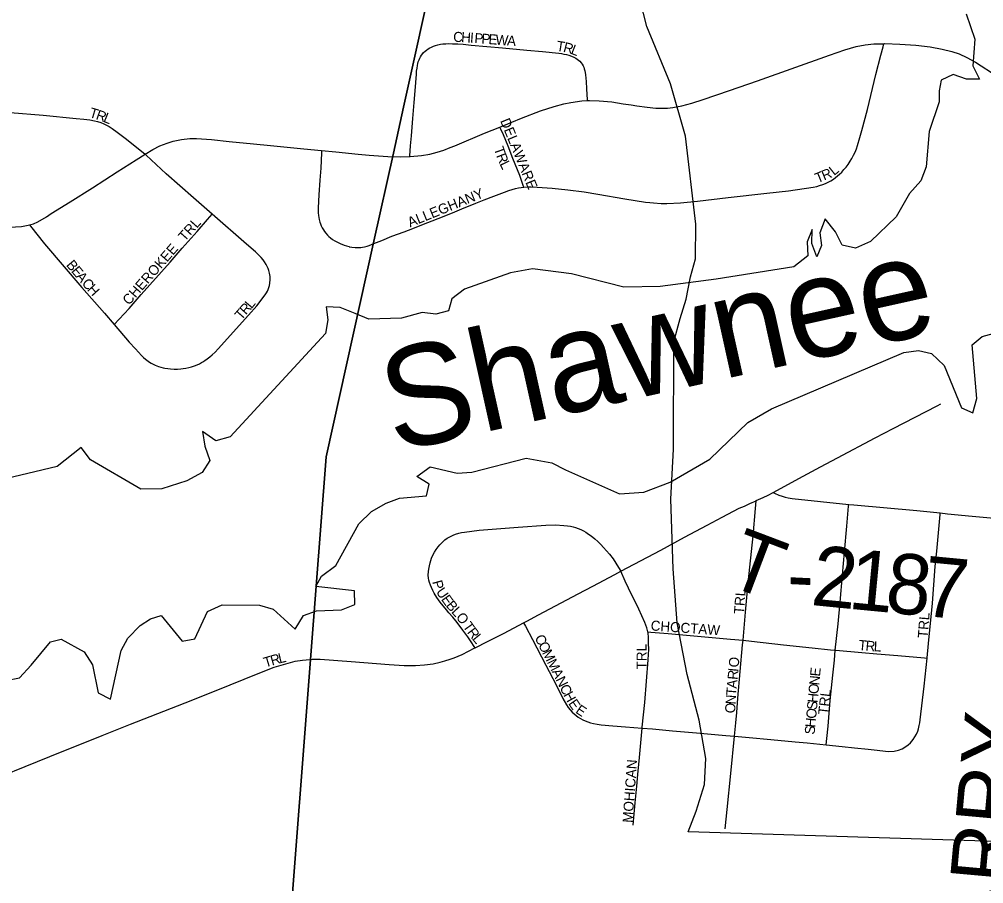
# Model space of a CAD drawing. Extents: x -5.4 to 49.9, y 13.2 to 48.4.
# Drawn here: x 27.015 to 27.924, y 42.711 to 43.526 of the extents above; entities that cross this region are included whole.
import ezdxf

# ---------------------------------------------------------------- set-up
doc = ezdxf.new("R2010")
doc.units = 0
for name, color, linetype in [('GM_X_Corporation', 7, 'Continuous'), ('GM_X_County_Road_Text', 7, 'Continuous'), ('GM_X_Major_Lake', 7, 'Continuous'), ('GM_X_Major_Lake_Text', 7, 'Continuous'), ('GM_X_Township', 7, 'Continuous'), ('GM_X_Township_Road', 7, 'Continuous'), ('GM_X_Township_Road_Text', 7, 'Continuous'), ('GM_X_Township_Subdivision', 7, 'Continuous'), ('GM_X_Township_Subdivision_Text', 7, 'Continuous')]:
    doc.layers.add(name, color=color, linetype=linetype)

msp = doc.modelspace()

# ---------------------------------------------------------------- linework, layer by layer
at = {"layer": 'GM_X_Corporation'}
msp.add_lwpolyline([(28.56624, 42.73136), (27.6459, 42.76038), (27.65346, 42.77968), (27.66125, 42.80482), (27.66239, 42.8295), (27.65632, 42.86559), (27.64493, 42.90851), (27.63544, 42.95751), (27.63165, 43.0084), (27.62938, 43.07411), (27.63204, 43.1212), (27.63225, 43.22236), (27.63841, 43.24417), (27.64404, 43.26266), (27.64805, 43.28356), (27.65287, 43.30045), (27.65294, 43.33325), (27.64345, 43.4163), (27.62902, 43.46569), (27.607, 43.51963), (27.59725, 43.55802)], dxfattribs=at)
at = {"layer": 'GM_X_Major_Lake'}
for points in [[(27.90786, 43.5315), (27.91605, 43.50779), (27.91435, 43.4824), (27.92052, 43.47012), (27.90838, 43.47001), (27.89559, 43.47447), (27.88448, 43.46902), (27.88236, 43.45882), (27.88251, 43.44857), (27.87317, 43.4207), (27.87015, 43.38737), (27.86531, 43.37419), (27.85442, 43.36229), (27.8418, 43.34018), (27.81778, 43.3168), (27.80361, 43.31066), (27.79116, 43.31359), (27.78461, 43.32588), (27.77503, 43.33823), (27.76981, 43.32506), (27.77144, 43.31326), (27.76703, 43.30236), (27.76238, 43.31498), (27.76268, 43.32826), (27.75787, 43.3166), (27.75871, 43.3033), (27.74559, 43.29296), (27.67216, 43.2813), (27.61932, 43.27449), (27.58518, 43.27372), (27.5358, 43.28657), (27.49913, 43.29117), (27.4782, 43.28745), (27.43502, 43.27208), (27.42306, 43.26286), (27.41978, 43.25155), (27.40795, 43.24839), (27.39509, 43.24982), (27.37564, 43.24455), (27.34492, 43.24371), (27.33176, 43.24893), (27.31786, 43.25455), (27.30461, 43.25522), (27.30623, 43.24304), (27.30405, 43.23019), (27.21392, 43.13275), (27.20057, 43.12887), (27.18788, 43.13787), (27.19022, 43.12378), (27.19485, 43.1104), (27.18778, 43.09917), (27.17319, 43.09114), (27.14952, 43.08369), (27.1298, 43.08337), (27.08227, 43.11098), (27.07343, 43.12255), (27.05104, 43.10483), (26.9954, 43.09164)], [(27.00256, 42.90289), (27.01552, 42.90564), (27.0264, 42.91754), (27.04471, 42.93953), (27.05461, 42.94197), (27.07634, 42.9301), (27.08441, 42.91778), (27.08951, 42.89149), (27.10112, 42.88554), (27.11124, 42.93123), (27.11757, 42.94286), (27.12921, 42.95475), (27.13882, 42.96098), (27.14913, 42.96417), (27.16869, 42.94022), (27.18086, 42.94223), (27.19281, 42.96815), (27.2066, 42.9743), (27.24185, 42.9739), (27.25465, 42.9702), (27.27547, 42.95153), (27.28334, 42.96426), (27.29556, 42.96855), (27.31909, 42.96955), (27.33171, 42.97458), (27.33124, 42.98749), (27.29494, 42.99171), (27.30009, 43.00146), (27.31358, 43.01141), (27.33531, 43.05077), (27.34731, 43.06227), (27.36114, 43.07032), (27.37376, 43.07497), (27.3992, 43.07707), (27.40172, 43.08802), (27.39013, 43.09548), (27.40246, 43.10432), (27.42811, 43.09844), (27.44178, 43.09928), (27.49325, 43.11257), (27.51742, 43.10825), (27.53016, 43.10151), (27.58122, 43.07914), (27.604, 43.08054), (27.62885, 43.08986), (27.66611, 43.11181), (27.70214, 43.14631), (27.72441, 43.1591), (27.84918, 43.21214), (27.86287, 43.21412), (27.87532, 43.21119), (27.8872, 43.19992), (27.90337, 43.1601), (27.91426, 43.15531), (27.91797, 43.16889), (27.91341, 43.21946), (27.92306, 43.22721), (27.95625, 43.23635)]]:
    msp.add_lwpolyline(points, dxfattribs=at)
at = {"layer": 'GM_X_Township'}
for points in [[(27.24718, 42.36774), (27.29015, 42.92693), (27.30451, 43.11387), (27.34959, 43.3173), (27.36795, 43.40015), (27.3776, 43.4437), (27.55837, 44.25954)], [(27.55837, 44.25954), (27.3776, 43.4437), (27.36795, 43.40015), (27.34959, 43.3173), (27.30451, 43.11387), (27.29015, 42.92693), (27.24718, 42.36774)]]:
    msp.add_lwpolyline(points, dxfattribs=at)
at = {"layer": 'GM_X_Township_Road'}
for points in [[(27.55082, 43.44977), (27.55286, 43.4499), (27.56203, 43.44954), (27.57372, 43.44848), (27.58467, 43.44686), (27.59194, 43.44567), (27.59742, 43.44484), (27.60723, 43.44341), (27.61528, 43.4427), (27.62217, 43.44258), (27.62648, 43.44275), (27.63144, 43.44325), (27.63976, 43.44478), (27.6494, 43.44726), (27.66004, 43.45071), (27.68472, 43.45924), (27.71111, 43.46841), (27.77896, 43.49268), (27.79366, 43.49761), (27.80436, 43.50063), (27.81281, 43.50231), (27.82076, 43.50318), (27.83034, 43.50342)], [(27.83034, 43.50342), (27.83124, 43.50345), (27.84549, 43.50311), (27.86032, 43.50207), (27.87383, 43.50041), (27.8854, 43.49834), (27.89437, 43.4961), (27.90133, 43.49371), (27.9086, 43.49041), (27.91666, 43.48587), (27.93699, 43.47281)], [(27.46826, 43.42481), (27.47969, 43.42951), (27.48885, 43.43316), (27.50665, 43.44001), (27.51955, 43.44429), (27.52849, 43.44659), (27.53514, 43.44793), (27.54553, 43.44941), (27.55082, 43.44977)], [(27.38333, 43.39701), (27.38376, 43.39702), (27.39435, 43.39801), (27.40237, 43.39934), (27.40907, 43.401), (27.4156, 43.40316), (27.42137, 43.40543), (27.42598, 43.40725), (27.45396, 43.41893), (27.46826, 43.42481)], [(27.13392, 43.39922), (27.14111, 43.40367), (27.14771, 43.40697), (27.15454, 43.40974), (27.16036, 43.41155), (27.16817, 43.41307), (27.17611, 43.41398), (27.1822, 43.41412), (27.19635, 43.41297), (27.21302, 43.4113), (27.23592, 43.40911), (27.25195, 43.4075), (27.28341, 43.40438), (27.30017, 43.40268)], [(27.02492, 43.33258), (27.02854, 43.33368), (27.0326, 43.33546), (27.04079, 43.3401), (27.04544, 43.34322), (27.06314, 43.35436), (27.08425, 43.36764), (27.10757, 43.3825), (27.12534, 43.39391), (27.13392, 43.39922)], [(27.30017, 43.40268), (27.31366, 43.40131), (27.33476, 43.39929)], [(27.33476, 43.39929), (27.34519, 43.3983), (27.36256, 43.39702), (27.37441, 43.39673), (27.38333, 43.39701)], [(26.99436, 43.32999), (27.0118, 43.33078), (27.01744, 43.33118), (27.02367, 43.33221), (27.02492, 43.33258)], [(27.72606, 43.08009), (27.72737, 43.07951), (27.73143, 43.07773), (27.7343, 43.07664), (27.73727, 43.07584), (27.74014, 43.07525), (27.74397, 43.07468), (27.79724, 43.069)], [(27.79724, 43.069), (27.80209, 43.06849), (27.86153, 43.06314), (27.88335, 43.06095)], [(27.88335, 43.06095), (27.89044, 43.06024), (27.91351, 43.05792), (27.96863, 43.05303), (27.98907, 43.05107), (28.00831, 43.0493), (28.01008, 43.04914)]]:
    msp.add_lwpolyline(points, dxfattribs=at)
at = {"layer": 'GM_X_Township_Subdivision'}
for points in [[(27.38333, 43.39701), (27.38339, 43.39774), (27.38415, 43.40712), (27.38491, 43.41662), (27.38623, 43.43299), (27.38749, 43.448), (27.38836, 43.45898), (27.38956, 43.47453), (27.38981, 43.47754), (27.3902, 43.48018), (27.39067, 43.48294), (27.39103, 43.48467), (27.39141, 43.48627), (27.39212, 43.48814), (27.39289, 43.48974), (27.39356, 43.49098), (27.39456, 43.49263), (27.39557, 43.4941), (27.39642, 43.49513), (27.39774, 43.49631), (27.39912, 43.49744), (27.40066, 43.49856), (27.40223, 43.49951), (27.40374, 43.50027), (27.4056, 43.50105), (27.40753, 43.50174), (27.40975, 43.50232), (27.41228, 43.5029), (27.41465, 43.50316), (27.41729, 43.50335), (27.42022, 43.50347), (27.42371, 43.50338), (27.42878, 43.50316), (27.43359, 43.50284), (27.44124, 43.50213), (27.47088, 43.49941), (27.49372, 43.49742), (27.50853, 43.4961), (27.52393, 43.49442), (27.52639, 43.49404), (27.52848, 43.49365), (27.53126, 43.49308), (27.53343, 43.49257), (27.53587, 43.4918), (27.53799, 43.49083), (27.53985, 43.48987), (27.54126, 43.48891), (27.54254, 43.48788), (27.54362, 43.48686), (27.54498, 43.48544), (27.54597, 43.48402), (27.54678, 43.48255), (27.54733, 43.48129), (27.54776, 43.47979), (27.54833, 43.47775), (27.5489, 43.47434), (27.54933, 43.47061), (27.54957, 43.46796), (27.5501, 43.46058), (27.55076, 43.45064), (27.55082, 43.44977)], [(27.49086, 43.36817), (27.49401, 43.3684), (27.49775, 43.36842), (27.50335, 43.36816), (27.50834, 43.36786), (27.51305, 43.3675), (27.51763, 43.36715), (27.53236, 43.36563), (27.54776, 43.3638), (27.5606, 43.36163), (27.58614, 43.357), (27.60571, 43.35402), (27.60965, 43.35352), (27.61327, 43.35326), (27.62042, 43.35287), (27.6256, 43.35283), (27.63856, 43.35344), (27.65461, 43.355), (27.68361, 43.35838), (27.72002, 43.36247), (27.74041, 43.36482), (27.76369, 43.36824), (27.76699, 43.3689), (27.76964, 43.36965), (27.77266, 43.37062), (27.77539, 43.37167), (27.78028, 43.37411), (27.78293, 43.3758), (27.7848, 43.37715), (27.78853, 43.38026), (27.79066, 43.38238), (27.79273, 43.38464), (27.79469, 43.38698), (27.79651, 43.38942), (27.79863, 43.39257), (27.80009, 43.39512), (27.80176, 43.39816), (27.80316, 43.40101), (27.80447, 43.40441), (27.80551, 43.40728), (27.80768, 43.41485), (27.80957, 43.42159), (27.81474, 43.44132), (27.82288, 43.47451), (27.82755, 43.49262), (27.82954, 43.50034), (27.83034, 43.50342)], [(26.98934, 43.44019), (27.00649, 43.43859), (27.03764, 43.43588), (27.06877, 43.43298), (27.07594, 43.43232), (27.08162, 43.43152), (27.08606, 43.43062), (27.08894, 43.42996), (27.09214, 43.42897), (27.09502, 43.42774), (27.09749, 43.42651), (27.10003, 43.42519), (27.10283, 43.42346), (27.10764, 43.41985), (27.1164, 43.41327), (27.13392, 43.39922)], [(27.49086, 43.36817), (27.49063, 43.36883), (27.48895, 43.37361), (27.487, 43.37902), (27.4806, 43.39531), (27.47602, 43.40685), (27.47178, 43.41754), (27.46887, 43.42356), (27.46826, 43.42481)], [(27.19709, 43.34282), (27.17941, 43.3582), (27.15356, 43.38058), (27.13481, 43.39839), (27.13392, 43.39922)], [(27.30017, 43.40268), (27.30008, 43.40063), (27.29949, 43.38618), (27.29862, 43.37485), (27.29757, 43.36092), (27.29725, 43.35483), (27.29692, 43.34835), (27.29698, 43.34588), (27.2971, 43.34379), (27.29726, 43.3414), (27.29759, 43.33943), (27.29789, 43.33776), (27.29858, 43.33507), (27.29909, 43.33358), (27.29977, 43.33178), (27.3008, 43.32973), (27.30191, 43.32792), (27.30299, 43.3262), (27.30421, 43.32463), (27.30567, 43.32299), (27.30712, 43.32159), (27.30865, 43.32024), (27.31062, 43.31887), (27.31282, 43.31761), (27.31532, 43.31636), (27.31773, 43.31516), (27.32168, 43.31355), (27.32377, 43.31271), (27.32608, 43.31206)], [(27.32608, 43.31206), (27.32626, 43.31202), (27.32867, 43.31156), (27.33183, 43.31123), (27.33356, 43.31111), (27.3359, 43.31123), (27.3373, 43.31131), (27.33881, 43.31152), (27.34079, 43.31193), (27.34321, 43.31263), (27.34507, 43.31325), (27.34938, 43.31497), (27.35689, 43.31797), (27.36658, 43.32185), (27.378, 43.32613), (27.38627, 43.32927), (27.39476, 43.33248), (27.41025, 43.33865), (27.42359, 43.34408), (27.43249, 43.34781), (27.44555, 43.35308), (27.45353, 43.35613), (27.46261, 43.35961), (27.4726, 43.36351), (27.47676, 43.36497), (27.47981, 43.36596), (27.4832, 43.36688), (27.48587, 43.36752), (27.48834, 43.36791), (27.49086, 43.36817)], [(27.10474, 43.23854), (27.11894, 43.22185), (27.1247, 43.21569), (27.13043, 43.20941), (27.13248, 43.20738), (27.13413, 43.20592), (27.13548, 43.20488), (27.13668, 43.20398), (27.13789, 43.20317), (27.13943, 43.20218), (27.14149, 43.20111), (27.14349, 43.20019), (27.14646, 43.19905), (27.14876, 43.19835), (27.15098, 43.19781), (27.15258, 43.19753), (27.15528, 43.19715), (27.15793, 43.19687), (27.16138, 43.19664), (27.16433, 43.19663), (27.16749, 43.19676), (27.16985, 43.19704), (27.17235, 43.1974), (27.17506, 43.19798), (27.17772, 43.19872), (27.18032, 43.19963), (27.18283, 43.20061), (27.18509, 43.20164), (27.18701, 43.20268), (27.18834, 43.20341), (27.19027, 43.20472), (27.19236, 43.20615), (27.195, 43.20826), (27.19709, 43.2101), (27.19976, 43.21265), (27.2028, 43.21564), (27.23142, 43.24752), (27.23918, 43.25633), (27.24717, 43.26653), (27.24832, 43.26843), (27.24924, 43.27017), (27.24989, 43.27171), (27.25049, 43.27353), (27.25104, 43.27534), (27.25136, 43.27764), (27.2517, 43.28109), (27.25161, 43.28397), (27.25104, 43.28709), (27.25049, 43.28951), (27.24989, 43.29136), (27.24888, 43.2934), (27.24799, 43.29523), (27.24649, 43.29761), (27.24504, 43.29966), (27.24313, 43.30191), (27.23793, 43.30715), (27.22959, 43.31453), (27.19709, 43.34282)], [(27.10474, 43.23854), (27.10954, 43.24374), (27.1188, 43.25377), (27.13026, 43.26685), (27.15737, 43.29754), (27.16891, 43.31054), (27.18294, 43.32626), (27.1926, 43.33756), (27.19709, 43.34282)], [(27.02492, 43.33258), (27.02589, 43.33135), (27.0391, 43.31459), (27.07429, 43.2736), (27.0956, 43.24929), (27.10474, 43.23854)], [(27.72606, 43.08009), (27.75416, 43.09569), (27.77059, 43.10447), (27.7865, 43.11287), (27.82217, 43.13174), (27.83923, 43.14067), (27.88065, 43.16203), (27.88396, 43.1637)], [(27.70985, 43.0725), (27.71, 43.07257), (27.71641, 43.0754), (27.72109, 43.07767), (27.72606, 43.08009)], [(27.58247, 43.00602), (27.61997, 43.02589), (27.64233, 43.03804), (27.66362, 43.0496), (27.67796, 43.05705), (27.694, 43.06533), (27.69878, 43.06751), (27.70384, 43.06998), (27.70985, 43.0725)], [(27.69754, 42.94092), (27.69984, 42.96743), (27.70236, 42.99492), (27.70701, 43.03932), (27.70924, 43.06531), (27.70985, 43.0725)], [(27.78452, 42.93154), (27.7872, 42.95647), (27.78908, 42.97682), (27.79147, 43.00257), (27.79326, 43.02409), (27.79542, 43.04854), (27.79709, 43.06741), (27.79724, 43.069)], [(27.87112, 42.92412), (27.87115, 42.92442), (27.87242, 42.93778), (27.87604, 42.97581), (27.87869, 43.01062), (27.8801, 43.0249), (27.88327, 43.05941), (27.88335, 43.06095)], [(27.44487, 42.93386), (27.44409, 42.93508), (27.44124, 42.93948), (27.43798, 42.94421), (27.43349, 42.95049), (27.42984, 42.95527), (27.42673, 42.95913), (27.4239, 42.96264), (27.4203, 42.96683), (27.41795, 42.96959), (27.41215, 42.9768), (27.40892, 42.98129), (27.40634, 42.9854), (27.40504, 42.98783), (27.40374, 42.99052), (27.40283, 42.9928), (27.40202, 42.99541), (27.40145, 42.99754), (27.40109, 42.99955), (27.4008, 43.00218), (27.40096, 43.00561), (27.40131, 43.00789), (27.40186, 43.01115), (27.40251, 43.01393), (27.40316, 43.01621), (27.40398, 43.01841), (27.40512, 43.02102), (27.40675, 43.02412), (27.40838, 43.0264), (27.4102, 43.02896), (27.41173, 43.03097), (27.4138, 43.03309), (27.41645, 43.03548), (27.41874, 43.03708), (27.42054, 43.0381), (27.42224, 43.03896), (27.42431, 43.03999), (27.42648, 43.04092), (27.42948, 43.04179), (27.43219, 43.04246), (27.43483, 43.04298), (27.44895, 43.04473), (27.48548, 43.0476), (27.5115, 43.04944), (27.52075, 43.04964), (27.52873, 43.04921), (27.53199, 43.04891), (27.53501, 43.04842), (27.53754, 43.04785), (27.5395, 43.04727), (27.54203, 43.04638), (27.54462, 43.0453), (27.547, 43.0441), (27.54947, 43.04275), (27.55197, 43.04108), (27.55447, 43.03932), (27.55784, 43.03644), (27.56054, 43.03414), (27.56339, 43.03137), (27.56616, 43.02849), (27.57152, 43.02207), (27.57505, 43.0176), (27.57763, 43.01376), (27.58023, 43.0096), (27.58247, 43.00602)], [(27.49073, 42.95744), (27.49377, 42.95905), (27.5047, 42.96494), (27.54201, 42.98468), (27.5561, 42.99207), (27.57666, 43.00286), (27.58247, 43.00602)], [(27.60779, 42.94876), (27.60697, 42.95268), (27.60495, 42.95778), (27.59927, 42.97018), (27.58948, 42.98998), (27.58642, 42.99676), (27.58247, 43.00602)], [(27.44487, 42.93386), (27.45662, 42.93976), (27.47239, 42.94768), (27.49073, 42.95744)], [(27.49073, 42.95744), (27.49235, 42.95435), (27.499, 42.94172), (27.51165, 42.91749), (27.52146, 42.8988), (27.5278, 42.886), (27.53117, 42.88006), (27.53278, 42.87753), (27.53451, 42.87532), (27.53632, 42.87326), (27.53821, 42.8717), (27.54018, 42.86989), (27.54225, 42.86844), (27.54437, 42.86718), (27.54653, 42.86593), (27.54881, 42.86496), (27.55112, 42.86403), (27.55374, 42.86315), (27.5565, 42.86252), (27.55999, 42.86183), (27.56385, 42.8613), (27.57496, 42.86026), (27.58671, 42.85917), (27.60246, 42.85799)], [(27.60246, 42.85799), (27.60254, 42.85893), (27.60485, 42.88235), (27.60803, 42.92253), (27.60859, 42.93237), (27.60857, 42.93794), (27.60837, 42.94351), (27.60799, 42.94783), (27.60779, 42.94876)], [(27.60779, 42.94876), (27.61069, 42.94853), (27.62701, 42.94725), (27.65113, 42.94513), (27.68579, 42.94201), (27.69754, 42.94092)], [(27.28907, 42.92279), (27.29147, 42.92302), (27.29894, 42.92314), (27.3282, 42.92089), (27.36394, 42.91814), (27.37815, 42.91724), (27.38864, 42.91716), (27.39725, 42.91769), (27.40538, 42.91881), (27.41204, 42.92017), (27.41658, 42.92144), (27.42141, 42.923), (27.4253, 42.9244), (27.43275, 42.92744), (27.44479, 42.93382), (27.44487, 42.93386)], [(27.68962, 42.8504), (27.69088, 42.86301), (27.69177, 42.87287), (27.69276, 42.88646), (27.69716, 42.93656), (27.69754, 42.94092)], [(27.69754, 42.94092), (27.70546, 42.94006), (27.73582, 42.93677), (27.7626, 42.93385), (27.78016, 42.93193), (27.78452, 42.93154)], [(27.77594, 42.84227), (27.77671, 42.8484), (27.77788, 42.85979), (27.77983, 42.88419), (27.78231, 42.90799), (27.78365, 42.92227), (27.78452, 42.93154)], [(27.77594, 42.84227), (27.79099, 42.84069), (27.80272, 42.83945), (27.81548, 42.83811), (27.82396, 42.8372), (27.83191, 42.83635), (27.83487, 42.83619), (27.83989, 42.83644), (27.84408, 42.83742), (27.84762, 42.83866), (27.85115, 42.84079), (27.85337, 42.84235), (27.85543, 42.84433), (27.85659, 42.84576), (27.85789, 42.84737), (27.85962, 42.84991), (27.86109, 42.85246), (27.86233, 42.85518), (27.86305, 42.85756), (27.86375, 42.86045), (27.86422, 42.86315), (27.86466, 42.866), (27.86838, 42.89772), (27.87112, 42.92412)], [(27.78452, 42.93154), (27.785, 42.93152), (27.80965, 42.92939), (27.82371, 42.92818), (27.84362, 42.92648), (27.86849, 42.92434), (27.87112, 42.92412)], [(26.94884, 42.7932), (26.96214, 42.79844), (26.98522, 42.80767), (26.99906, 42.81317), (27.02072, 42.82186), (27.04399, 42.83121), (27.09353, 42.85109), (27.12002, 42.86175), (27.17718, 42.88426), (27.21402, 42.89898), (27.24043, 42.90974), (27.25551, 42.91543), (27.26198, 42.91745), (27.26863, 42.91947), (27.27533, 42.92107), (27.2822, 42.92214), (27.28907, 42.92279)], [(27.59392, 42.76668), (27.59493, 42.77741), (27.59591, 42.78773), (27.59739, 42.8034), (27.59847, 42.81449), (27.59847, 42.81455), (27.59961, 42.82681), (27.60246, 42.85799)], [(27.60246, 42.85799), (27.6121, 42.85728), (27.63118, 42.85561), (27.65354, 42.85364), (27.68138, 42.8511), (27.68962, 42.8504)], [(27.68075, 42.76303), (27.68262, 42.78128), (27.68614, 42.81543), (27.68962, 42.8504)], [(27.68962, 42.8504), (27.70348, 42.84923), (27.72371, 42.84727), (27.74656, 42.84523), (27.75808, 42.84407), (27.77594, 42.84227)]]:
    msp.add_lwpolyline(points, dxfattribs=at)

# ---------------------------------------------------------------- texts
at = {"layer": 'GM_X_County_Road_Text'}
msp.add_text('QUARRY', height=0.056818, rotation=84.81718, dxfattribs=at).set_placement((27.93436, 42.54617))
at = {"layer": 'GM_X_Major_Lake_Text'}
msp.add_text('Shawnee', height=0.094693, rotation=12.51691, dxfattribs=at).set_placement((27.36868, 43.11808))
at = {"layer": 'GM_X_Township_Road_Text'}
for s, rotation, p in [('T', 339.22927, (27.67928, 42.99437)), ('2', 354.36035, (27.76058, 42.97429)), ('1', 354.50831, (27.79557, 42.97083)), ('8', 354.54193, (27.83045, 42.96748)), ('7', 354.54887, (27.8653, 42.96415)), ('-', 357.27201, (27.73803, 42.97534))]:
    msp.add_text(s, height=0.05682, rotation=rotation, dxfattribs=at).set_placement(p)
at = {"layer": 'GM_X_Township_Subdivision_Text'}
for s, rotation, p in [('C', 357.88699, (27.42416, 43.50523)), ('H', 355.99692, (27.43158, 43.50496)), ('I', 355.71194, (27.43988, 43.50438)), ('P', 355.73481, (27.44404, 43.50407)), ('P', 355.73481, (27.45068, 43.50357)), ('E', 355.73481, (27.45733, 43.50308)), ('W', 355.7388, (27.46398, 43.50258)), ('A', 355.73373, (27.47478, 43.50178)), ('T', 350.9734, (27.52113, 43.49688)), ('R', 345.71634, (27.52749, 43.49588)), ('L', 338.7212, (27.53447, 43.49413)), ('T', 343.25888, (27.08055, 43.43433)), ('R', 340.69735, (27.08682, 43.43245)), ('L', 338.04639, (27.09379, 43.43001)), ('DELAWARE', 292.33732, (27.46842, 43.43076)), ('T', 289.49763, (27.46241, 43.40451)), ('R', 291.0426, (27.46473, 43.39796)), ('L', 296.18505, (27.46778, 43.39013)), ('L', 38.82943, (27.78336, 43.37863)), ('T', 22.33407, (27.76774, 43.37176)), ('R', 22.35845, (27.77391, 43.3743)), ('ALLEGHANY', 22.16566, (27.38359, 43.3301)), ('TRL', 48.1842, (27.17126, 43.3163)), ('CHEROKEE', 48.74526, (27.11872, 43.25625)), ('B', 309.82423, (27.05896, 43.29459)), ('E', 309.85399, (27.06377, 43.28882)), ('A', 309.83076, (27.06804, 43.28371)), ('C', 311.44087, (27.07357, 43.27708)), ('H', 312.65859, (27.07868, 43.2713)), ('L', 50.23418, (27.23412, 43.253)), ('T', 48.74983, (27.2246, 43.24214)), ('R', 48.77824, (27.229, 43.24716)), ('P', 285.14968, (27.40446, 42.99613)), ('U', 304.57043, (27.40767, 42.98653)), ('TRL', 85.60322, (27.69832, 42.96525)), ('E', 305.80168, (27.41253, 42.97948)), ('B', 310.04105, (27.4169, 42.97347)), ('L', 312.68057, (27.42204, 42.96737)), ('O', 307.91908, (27.42642, 42.96263)), ('TRL', 85.60322, (27.87165, 42.94275)), ('T', 305.38526, (27.43293, 42.9541)), ('R', 307.34595, (27.437, 42.94838)), ('CHOCTAW', 355.91283, (27.61026, 42.95023)), ('L', 309.38536, (27.44177, 42.94213)), ('C', 296.58678, (27.50083, 42.94344)), ('O', 296.60021, (27.50419, 42.93673)), ('TRL', 90, (27.60664, 42.91345)), ('T', 354.77341, (27.8061, 42.93189)), ('R', 354.77039, (27.81274, 42.93128)), ('L', 357.13994, (27.82063, 42.93057)), ('T', 16.30937, (27.24709, 42.91516)), ('R', 15.89202, (27.25347, 42.91703)), ('L', 13.40009, (27.26057, 42.91905)), ('M', 296.60578, (27.50792, 42.92928)), ('M', 296.58949, (27.5124, 42.92034)), ('O', 84.81239, (27.69336, 42.91499)), ('E', 84.3628, (27.77008, 42.90646)), ('A', 296.60021, (27.51688, 42.9114)), ('N', 296.60415, (27.52061, 42.90395)), ('R', 84.79677, (27.6923, 42.90337)), ('I', 84.78973, (27.69298, 42.91084)), ('N', 84.65913, (27.76931, 42.89817)), ('C', 296.58678, (27.52434, 42.8965)), ('T', 85.07523, (27.69098, 42.88844)), ('A', 84.81348, (27.69155, 42.89507)), ('O', 84.67617, (27.76853, 42.88988)), ('H', 298.79819, (27.52788, 42.88944)), ('N', 86.28187, (27.69044, 42.88018)), ('H', 84.66564, (27.76776, 42.88158)), ('TRL', 83.41358, (27.77768, 42.87042)), ('E', 304.41507, (27.53243, 42.88127)), ('E', 325.93373, (27.53894, 42.87305)), ('O', 86.785, (27.68998, 42.87188)), ('S', 84.66897, (27.76714, 42.87494)), ('O', 84.65913, (27.76636, 42.86664)), ('S', 84.66457, (27.76497, 42.85171)), ('H', 84.65913, (27.76559, 42.85834)), ('MOHICAN', 85.7307, (27.59331, 42.76857))]:
    msp.add_text(s, height=0.00947, rotation=rotation, dxfattribs=at).set_placement(p)

doc.saveas('drawing.dxf')
